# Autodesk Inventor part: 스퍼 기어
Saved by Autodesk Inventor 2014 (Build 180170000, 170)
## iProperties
Created: 2026-08
Part Number: 스퍼 기어
Material: 강철, 합금
Document SubType Name: Modeling
Designer: dg
Density: 7.85 g/cm^3
Appearance: 반연마
Mass: 218.445 g
Surface Area: 146.846 cm^2
Volume: 27.8274 cm^3
Author: jhkim
Creation Date: 2026-07-31
Sending System: Autodesk Inventor 2027
Preprocessor: ST-DEVELOPER v20.1
Author: dg
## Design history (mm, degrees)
node "스퍼 기어1"
node "솔리드1"
node "기준1"
